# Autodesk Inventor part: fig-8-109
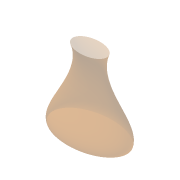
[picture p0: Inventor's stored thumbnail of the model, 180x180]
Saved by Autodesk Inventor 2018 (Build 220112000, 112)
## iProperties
Created: 2004-05
Part Number: fig-8-109
Document SubType Name: Modeling
Designer: CADCIM Technologies
Manufacturer: Standard
Standards Organization: Custom
Density: 1 g/cm^3
Material: Generic
Appearance: Default
Author: CADCIM Technologies
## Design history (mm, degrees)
sketch "Sketch4"
  geometry: 1 further point; 1 other entity
  constraints: 2 other
workplane "Work Plane2"
sketch "Sketch5"
  geometry: 1 further point; 1 other entity
  constraints: 2 other
feature "LoftSrf1" sketch "Sketch5" dims "d4" = 20, "d5" = 110 deg, "d6" = 40, "d7" = 70 deg
patch "Boundary Patch1" dims "d8" = 0, "d9" = 0
body "Srf1"
body "Srf2"
other parameters: "d3" = 33.5
